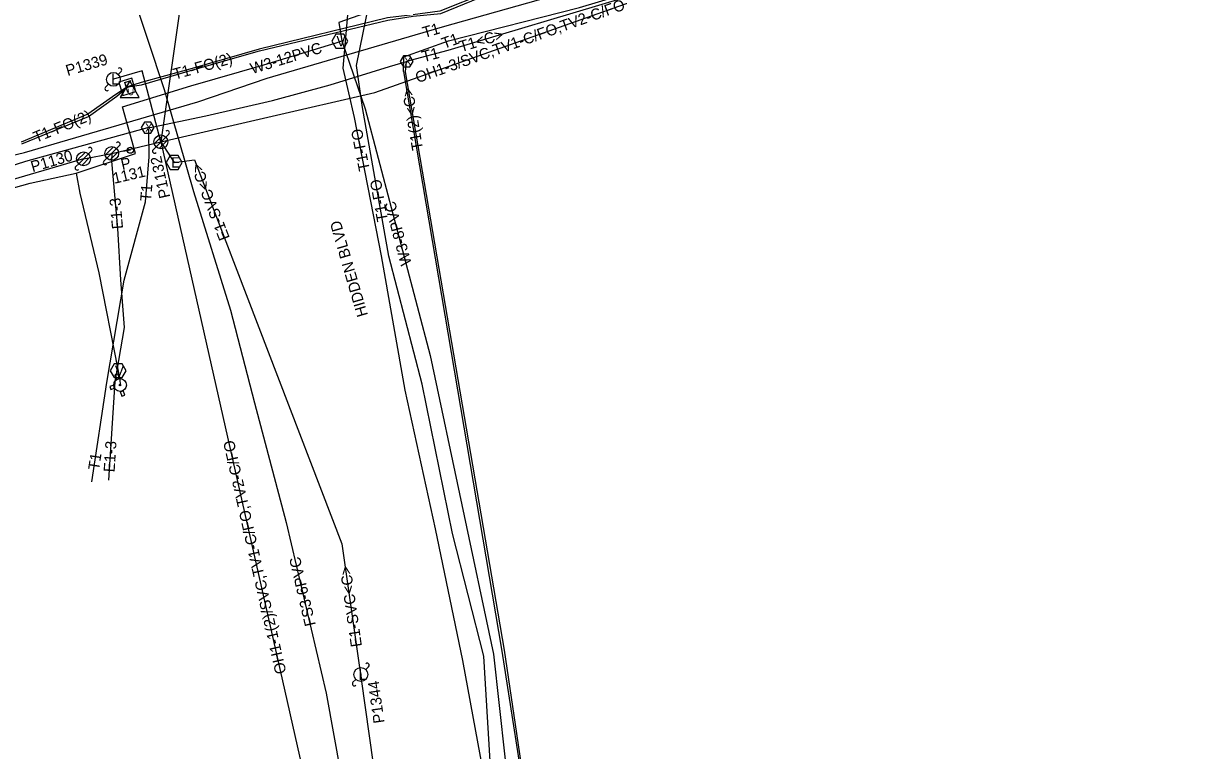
# Model space of a CAD drawing. Extents: x 2336688 to 2352634, y 362473 to 369571.
# Drawn here: x 2346759.7 to 2347179.1, y 366916.1 to 367179.3 of the extents above; entities that cross this region are included whole.
import ezdxf

# ---------------------------------------------------------------- set-up
doc = ezdxf.new("R2010")
doc.units = 0
for name, color, linetype in [('RD_EX_DV_Prop', 7, 'Continuous'), ('RD_EX_DV_TX_Prop', 7, 'Continuous'), ('RD_EX_RW', 7, 'Continuous'), ('RD_EX_RW_TX', 7, 'Continuous'), ('RD_HC_Data_Tic', 7, 'Continuous'), ('RD_PD_CstnLmt', 7, 'Continuous'), ('RD_PD_Final_TrvlWay', 7, 'Continuous'), ('RD_PD_PatLn3', 7, 'Continuous'), ('RD_PD_PatLn4', 7, 'Continuous'), ('RD_SHT_ShtClip', 7, 'Continuous'), ('RD_Sketch1', 7, 'Continuous'), ('RD_Sketch2', 7, 'Continuous'), ('RD_Sketch5', 7, 'Continuous'), ('RD_TX_Misc1', 7, 'Continuous')]:
    doc.layers.add(name, color=color, linetype=linetype)

# ---------------------------------------------------------------- blocks, each defined once
blk = doc.blocks.new('GW')
at = {"layer": 'RD_HC_Data_Tic'}
blk.add_line((0, 0), (0, 5), dxfattribs=at)
blk.add_circle((0, 0), 2, dxfattribs=at)

msp = doc.modelspace()

# ---------------------------------------------------------------- linework, layer by layer
at = {"layer": 'RD_EX_RW_TX'}
msp.add_line((2346913.35, 367169.48), (2347148.27, 367240), dxfattribs=at)
for points in [[(2346929.43, 366898.3), (2346926.24, 366950.27), (2346914.94, 366994.66), (2346903.95, 367048.72), (2346891.88, 367094.98), (2346882.43, 367148.75), (2346880.23, 367164.03), (2346885.05, 367187.76), (2346886.25, 367192.23), (2346889.58, 367192.85), (2346896.67, 367193.51), (2346947.77, 367206.59), (2346995.79, 367219.64), (2347046.69, 367235.53), (2347089.94, 367248.15), (2347136.19, 367262.43), (2347184.88, 367278.93), (2347230.19, 367297.47), (2347271.77, 367311.28), (2347325.01, 367320.63), (2347375.99, 367328.45), (2347424.9, 367338.06), (2347468.18, 367347.3), (2347525.21, 367359.4)], [(2346729.92, 367125.44), (2346760.09, 367132.46), (2346822.83, 367150.8), (2346847.92, 367159.43), (2346911.38, 367177.91), (2346957.67, 367191.14), (2346999.5, 367209.08), (2347049.12, 367224.56), (2347093.92, 367240.35), (2347120.7, 367252.77), (2347143.99, 367255.5), (2347186.71, 367269.91), (2347236.58, 367285.94), (2347255.06, 367289.24), (2347276.57, 367291.67), (2347281.58, 367292.99), (2347300.77, 367298.26), (2347328.04, 367305.43), (2347378.49, 367318.88), (2347428.36, 367324.58), (2347471.76, 367333.48), (2347528.47, 367342.27)], [(2346897.18, 367161.87), (2346897.33, 367167.15), (2346913.45, 367172.96), (2346960.85, 367184.91), (2347003.36, 367197.72), (2347054.81, 367213.14), (2347089.91, 367226.4), (2347147.29, 367244.91), (2347193.34, 367259.48), (2347243.62, 367272.38), (2347257.76, 367276.24), (2347278.69, 367281.44), (2347302.95, 367288.88), (2347331.85, 367293.13), (2347381.23, 367305.16), (2347429.75, 367317.72), (2347473.23, 367326.64), (2347527.97, 367334.66)], [(2347184.08, 367281.81), (2347138.56, 367267.72), (2347089.38, 367252.03), (2347046.03, 367236.73), (2346995.36, 367220.65), (2346947.88, 367207.83), (2346896.65, 367195.02), (2346889.86, 367192.06), (2346888.13, 367190.49), (2346885.89, 367189.55), (2346877.25, 367185.04), (2346875.24, 367162.99), (2346879.34, 367145.21), (2346889.15, 367095.18), (2346897.75, 367046.5), (2346908.64, 366996.35), (2346918.58, 366948.75), (2346927.75, 366898.93)], [(2347187.63, 367266.43), (2347137.4, 367253.23), (2347093.35, 367238.65), (2347047.24, 367230.28), (2346997.39, 367214.83), (2346954.54, 367201.39), (2346927.39, 367190.56), (2346910.36, 367183.58), (2346900.58, 367182.36), (2346891.43, 367181.19), (2346845.03, 367169.9), (2346819.99, 367162.67), (2346802.3, 367157.83), (2346797.35, 367156.24), (2346793.14, 367153.5), (2346783.01, 367146.37), (2346758.96, 367136.25)], [(2346759.16, 367135.67), (2346783.33, 367145.57), (2346793.56, 367152.89), (2346797.35, 367156.24), (2346802.42, 367157.05), (2346820.18, 367162.16), (2346845.16, 367169.26), (2346891.6, 367180.39), (2346900.69, 367181.78), (2346910.69, 367182.74), (2346927.88, 367189.94), (2346954.81, 367201.03), (2346997.5, 367214.34), (2347047.41, 367229.71), (2347093.48, 367238.02), (2347137.76, 367252.45), (2347187.57, 367265.92)], [(2346393.84, 367072.51), (2346446.37, 367073.84), (2346470.99, 367074.08), (2346475.1, 367074.82), (2346497.02, 367076.2), (2346550.51, 367084.4), (2346600.16, 367096.76), (2346658.08, 367107.59), (2346705.97, 367119.19), (2346717.24, 367119.65), (2346731.3, 367119.99), (2346760.58, 367129.35), (2346804.71, 367141.52), (2346806.24, 367141.63), (2346825.71, 367145.72), (2346849.8, 367151.32), (2346870.64, 367156.98), (2346892.17, 367163.68), (2346898.36, 367165.45), (2346899.77, 367165.87), (2346913.35, 367169.48)], [(2346960.84, 366700.32), (2346942.78, 366891.31), (2346933.69, 366952.5), (2346898, 367161.71), (2346898.36, 367165.45)], [(2346897.18, 367161.87), (2346932.76, 366952.15), (2346942.29, 366891.15), (2346960.4, 366700.28)], [(2346784.44, 367013.39), (2346789.98, 367049.33), (2346796.24, 367086.28), (2346803.91, 367114.61), (2346805.22, 367130.95), (2346805.06, 367140.37), (2346804.71, 367141.52)]]:
    msp.add_lwpolyline(points, dxfattribs=at)
for points in [[(2346900.67, 367165.45), (2346899.52, 367167.45), (2346897.21, 367167.45), (2346896.05, 367165.45), (2346897.21, 367163.45), (2346899.52, 367163.45)], [(2346799.01, 367159.35), (2346794.23, 367157.9), (2346795.69, 367153.12), (2346800.47, 367154.57)], [(2346807.02, 367141.52), (2346805.86, 367143.52), (2346803.55, 367143.52), (2346802.4, 367141.52), (2346803.55, 367139.52), (2346805.86, 367139.52)]]:
    msp.add_lwpolyline(points, close=True, dxfattribs=at)
at = {"layer": 'RD_HC_Data_Tic'}
for p, q in [((2346794.05, 367160.74), (2346795.11, 367161.8)), ((2346789.46, 367156.14), (2346790.52, 367157.2)), ((2346807.07, 367135.7), (2346810.13, 367138.77)), ((2346807.71, 367134.58), (2346811.25, 367138.12)), ((2346808.83, 367133.94), (2346811.9, 367137)), ((2346811.25, 367138.12), (2346812.31, 367139.18)), ((2346783.28, 367132.01), (2346784.34, 367133.07)), ((2346789.28, 367131.53), (2346792.34, 367134.6)), ((2346789.93, 367130.41), (2346793.46, 367133.95)), ((2346791.05, 367129.77), (2346794.11, 367132.83)), ((2346793.46, 367133.95), (2346794.53, 367135.01)), ((2346806.65, 367133.52), (2346807.71, 367134.58)), ((2346779.1, 367129.59), (2346782.16, 367132.65)), ((2346779.74, 367128.47), (2346783.28, 367132.01)), ((2346780.86, 367127.82), (2346783.93, 367130.89)), ((2346788.87, 367129.35), (2346789.93, 367130.41)), ((2346778.68, 367127.41), (2346779.74, 367128.47)), ((2346883.54, 366945.46), (2346884.6, 366946.52)), ((2346878.94, 366940.87), (2346880, 366941.93))]:
    msp.add_line(p, q, dxfattribs=at)
for centre in [(2346792.29, 367158.97), (2346809.48, 367136.35), (2346781.51, 367130.24), (2346791.7, 367132.18), (2346881.77, 366943.7)]:
    msp.add_circle(centre, 2.5, dxfattribs=at)
for centre, start, end in [((2346794.58, 367162.33), 315, 135), ((2346789.99, 367155.61), 135, 315), ((2346811.78, 367139.71), 315, 135), ((2346783.81, 367133.6), 315, 135), ((2346794, 367135.54), 315, 135), ((2346807.18, 367132.99), 135, 315), ((2346789.4, 367128.82), 135, 315), ((2346779.21, 367126.88), 135, 315), ((2346884.07, 366947.05), 315, 135), ((2346879.47, 366940.34), 135, 315)]:
    msp.add_arc(centre, 0.75, start, end, dxfattribs=at)
at = {"layer": 'RD_PD_Final_TrvlWay'}
for points in [[(2346809.48, 367136.35), (2346802.67, 367162.04), (2346792.33, 367159.03)], [(2346809.48, 367136.35), (2346814.29, 367128.92), (2346821.6, 367129.86), (2346874.93, 366991.01), (2346881.39, 366945.36), (2346881.77, 366943.7), (2346881.86, 366942.04), (2346903.9, 366786.54), (2346942.12, 366791.96), (2346944.96, 366791.65), (2346942.32, 366790.57), (2346904.1, 366785.15), (2346916.49, 366697.73)], [(2346791.7, 367132.18), (2346791.66, 367129.42), (2346793.8, 367105.02), (2346794.85, 367086.42), (2346796.25, 367069.18), (2346792.79, 367049.61), (2346790.55, 367013.96)]]:
    msp.add_lwpolyline(points, dxfattribs=at)
msp.add_lwpolyline([(2346817.18, 367128.92), (2346815.74, 367131.42), (2346812.85, 367131.42), (2346811.41, 367128.92), (2346812.85, 367126.42), (2346815.74, 367126.42)], close=True, dxfattribs=at)
at = {"layer": 'RD_PD_PatLn3'}
msp.add_lwpolyline([(2346798.21, 367158.45), (2346794.74, 367152.45), (2346801.67, 367152.45)], close=True, dxfattribs=at)
at = {"layer": 'RD_SHT_ShtClip'}
for p, q in [((2346837.29, 367330.12), (2346809.48, 367136.35)), ((2346791.7, 367132.18), (2346809.48, 367136.35)), ((2346809.48, 367136.35), (2346877.06, 366837.12)), ((2346781.51, 367130.24), (2346791.7, 367132.18))]:
    msp.add_line(p, q, dxfattribs=at)
for points in [[(2346809.48, 367136.35), (2346886.82, 367154.19), (2346987.08, 367189.8), (2347058.34, 367224.76)], [(2346781.51, 367130.24), (2346714.11, 367110.5), (2346535.66, 367073.8), (2346465.94, 367065.34)]]:
    msp.add_lwpolyline(points, dxfattribs=at)
at = {"layer": 'RD_Sketch2'}
for p, q in [((2346793.9, 367052.44), (2346792.8, 367052.07)), ((2346792.8, 367052.07), (2346793.38, 367050.31)), ((2346794.47, 367050.71), (2346793.9, 367052.44)), ((2346792.4, 367048.31), (2346790.98, 367047.84)), ((2346790.98, 367047.84), (2346791.34, 367046.75)), ((2346791.34, 367046.75), (2346792.74, 367047.21)), ((2346794.77, 367046.1), (2346795.34, 367044.4)), ((2346795.34, 367044.4), (2346796.43, 367044.76)), ((2346796.43, 367044.76), (2346795.88, 367046.42))]:
    msp.add_line(p, q, dxfattribs=at)
for points in [[(2346907.18, 367191.36), (2346873.77, 367179.55), (2346874.94, 367172.89), (2346883.31, 367148.26), (2346906.9, 367059.09), (2346929.73, 366951.1), (2346935.93, 366895.33), (2346950.72, 366767.23), (2346956.21, 366700.28)], [(2346558.16, 366973.72), (2346544.75, 367051.67), (2346541.37, 367068.09), (2346554.4, 367070.88), (2346601.18, 367082.55), (2346661, 367096.52), (2346709.36, 367106.7), (2346762.15, 367121.42), (2346778.82, 367125.01), (2346800.35, 367132.17), (2346795.56, 367149.03), (2346820.27, 367156.57), (2346846.65, 367164.22), (2346872.89, 367172.24), (2346874.94, 367172.89)], [(2346778.82, 367125.01), (2346780.18, 367117.76), (2346787.03, 367088.96), (2346793.85, 367053.99), (2346794.57, 367050.58), (2346794.71, 367048.41)]]:
    msp.add_lwpolyline(points, dxfattribs=at)
for points in [[(2346877.05, 367172.76), (2346875.6, 367175.26), (2346872.72, 367175.26), (2346871.27, 367172.76), (2346872.72, 367170.26), (2346875.6, 367170.26)], [(2346796.92, 367053.58), (2346795.47, 367056.08), (2346792.59, 367056.08), (2346791.14, 367053.58), (2346792.59, 367051.08), (2346795.47, 367051.08)]]:
    msp.add_lwpolyline(points, close=True, dxfattribs=at)
for radius in [2.31, 0.289]:
    msp.add_circle((2346794.71, 367048.41), radius, dxfattribs=at)
for start, end in [(95.9475, 124.9239), (182.5081, 211.4753), (271.6013, 300.5776)]:
    msp.add_arc((2346794.71, 367048.41), 2.31, start, end, dxfattribs=at)
at = {"layer": 'RD_Sketch5'}
msp.add_lwpolyline([(2346765.39, 367271.81), (2346776.02, 367241.77), (2346794.17, 367204.89), (2346798.54, 367192.2), (2346810.66, 367155.29), (2346821.32, 367118.37), (2346834.62, 367075.46), (2346843.34, 367041.99), (2346854.83, 366998.67), (2346869.3, 366936.93), (2346885.2, 366849.09), (2346899.13, 366743.03), (2346902.03, 366692.09)], dxfattribs=at)

# ---------------------------------------------------------------- block references
at = {"layer": 'RD_HC_Data_Tic', "xscale": 0.5546771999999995, "yscale": 0.5546771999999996, "rotation": 99.0070666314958}
msp.add_blockref('GW', (2346798.47, 367133.33), dxfattribs=at)

# ---------------------------------------------------------------- texts
at = {"layer": 'RD_EX_DV_Prop'}
for s, rotation, p in [('E1-SVC<C>', 111.0619, (2346834.46, 367101.64)), ('E1-3', 95.0296, (2346795.81, 367104.99)), ('E1-3', 86.3931, (2346792.73, 367016.77)), ('E1-SVC<C>', 98.0663, (2346882.2, 366953.94))]:
    msp.add_text(s, height=4, rotation=rotation, dxfattribs=at).set_placement(p)
at = {"layer": 'RD_EX_DV_TX_Prop'}
for s, rotation, p in [('P1339', 16.3203, (2346775.74, 367160.14)), ('P1130', 16.3203, (2346763.08, 367125.36)), ('P', 13.1933, (2346795.51, 367126.16)), ('P1132', 102.726, (2346812.9, 367116.42)), ('1131', 13.1933, (2346792.6, 367121.17)), ('P1344', 98.0663, (2346890.41, 366926.31))]:
    msp.add_text(s, height=4, rotation=rotation, dxfattribs=at).set_placement(p)
at = {"layer": 'RD_EX_RW'}
for s, rotation, p in [('T1', 16.2356, (2346904.74, 367173.9)), ('T1', 19.8115, (2346911.84, 367169.95)), ('T1<C>', 16.7097, (2346918.03, 367168.8)), ('T1-FO(2)', 15.8505, (2346814.56, 367158.84)), ('T1', 14.8954, (2346904.44, 367165.16)), ('T1(2)<C>', 99.6282, (2346904.34, 367133.65)), ('T1-FO(2)', 22.2858, (2346764.31, 367135.98)), ('T1-FO', 101.0988, (2346885.09, 367126.25)), ('T1', 85.4474, (2346805.93, 367114.74)), ('T1-FO', 99.9691, (2346891.65, 367107.87)), ('T1', 81.225, (2346787.08, 367017.4))]:
    msp.add_text(s, height=4, rotation=rotation, dxfattribs=at).set_placement(p)
at = {"layer": 'RD_EX_RW_TX'}
for p in [(2346897.42, 367163.95), (2346803.76, 367140.02)]:
    msp.add_text('X', height=3, dxfattribs=at).set_placement(p)
msp.add_text('F', height=4, rotation=16.9175, dxfattribs=at).set_placement((2346796.85, 367153.99))
at = {"layer": 'RD_HC_Data_Tic'}
for p in [(2346791.48, 367157.03), (2346880.96, 366941.76)]:
    msp.add_text('L', height=4, rotation=360, dxfattribs=at).set_placement(p)
at = {"layer": 'RD_PD_CstnLmt'}
for s, rotation, p in [('W3-12PVC', 16.9924, (2346842.51, 367160.86)), ('W3-8PVC', 104.815, (2346900.2, 367092.23))]:
    msp.add_text(s, height=4, rotation=rotation, dxfattribs=at).set_placement(p)
at = {"layer": 'RD_PD_Final_TrvlWay'}
msp.add_text('E', height=3.75, rotation=360, dxfattribs=at).set_placement((2346813.16, 367127.04))
at = {"layer": 'RD_PD_PatLn3'}
msp.add_text('U', height=2.4, dxfattribs=at).set_placement((2346797.45, 367153.25))
at = {"layer": 'RD_PD_PatLn4'}
for s, rotation, p in [('OH1-3/SVC,TV1-C/FO,TV2-C/FO', 19.5577, (2346902.36, 367157.58)), ('OH1-1(2)/SVC,TV1-C/FO,TV2-C/FO', 102.726, (2346854.89, 366944.37))]:
    msp.add_text(s, height=4, rotation=rotation, dxfattribs=at).set_placement(p)
at = {"layer": 'RD_Sketch1'}
msp.add_text('FS3-6PVC', height=4, rotation=103.1879, dxfattribs=at).set_placement((2346865.55, 366961.69))
at = {"layer": 'RD_Sketch2'}
for p in [(2346872.95, 367170.89), (2346792.82, 367051.7)]:
    msp.add_text('V', height=3.75, dxfattribs=at).set_placement(p)
at = {"layer": 'RD_TX_Misc1'}
msp.add_text('HIDDEN BLVD', height=4, rotation=106.2235, dxfattribs=at).set_placement((2346884.4, 367073.72))

doc.saveas('drawing.dxf')
